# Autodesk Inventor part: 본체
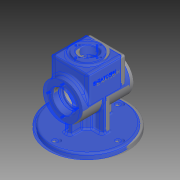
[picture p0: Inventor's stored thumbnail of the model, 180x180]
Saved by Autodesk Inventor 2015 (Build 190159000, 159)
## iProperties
Created: 2020-07
Part Number: 본체
Material: 알루미늄 6061
Document SubType Name: Modeling
Designer: mduedu
Density: 2.71 g/cm^3
Mass: 1025.32 g
Surface Area: 854.574 cm^2
Volume: 378.346 cm^3
Appearance: 기본값
Author: mduedu
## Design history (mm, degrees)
sketch "스케치1"
  geometry: C1 r 32 at (0, 0); 1 further point
  constraints: 1 centre point, 1 coincident
  dimensions: "d0" = 64 diameter of C1
extrude "돌출1" new body sketch "스케치1" stored distance "d1" = 90; taper "d2" = 0 deg
sketch "스케치3"
  geometry: L1 (0, -32)-(50, -32); L2 (50, -32)-(50, 32); L3 (50, 32)-(0, 32); L4 (0, 32)-(0, -32); C1 r 32 at (0, 0) reference; 2 further points
  constraints: 8 end point, 2 parallel, 1 coincident, 1 horizontal, 1 midpoint, 1 perpendicular, 1 tangent
  dimensions: "d5" = 50 distance of L2.end L3.end
extrude "돌출2" join sketch "스케치3" stored distance "d7" = 64; taper "d8" = 0 deg
sketch "스케치4"
  geometry: C1 r 25 at (32, 32); 1 further point
  constraints: 1 centre point, 1 coincident
  dimensions: "d9" = 50 diameter of C1
extrude "돌출3" join sketch "스케치4" distance "d10" = 5; taper "d11" = 0 deg
sketch "스케치5"
  geometry: L1 (0, -25)-(40, -25); L2 (40, -25)-(40, 25); L3 (40, 25)-(0, 25); L4 (0, 25)-(0, -25); L5 (55, -25)-(55, 25) reference; A1 r 25 centre (0, 0) between (0, 25) and (0, -25); A2 r 25 centre (0, 0) between (0, -25) and (0, 25); 2 further points
  constraints: 8 end point, 4 point on circle, 2 centre point, 2 coincident, 2 parallel, 1 horizontal, 1 midpoint, 1 perpendicular, 1 tangent
  dimensions: "d12" = 50 diameter of A1; "d13" = 15 distance between parallel lines of L2 L5
extrude "돌출4" cut sketch "스케치5" stored distance "d14" = 48; taper "d15" = 0 deg
sketch "스케치6"
  geometry: C1 r 20 at (0, 0); 1 further point
  constraints: 1 centre point, 1 coincident
  dimensions: "d16" = 40 diameter of C1
extrude "돌출5" cut sketch "스케치6" distance "d17" = 15; taper "d18" = 0 deg
sketch "스케치7"
  geometry: C1 r 17 at (0, 0); 1 further point
  constraints: 1 centre point, 1 coincident
  dimensions: "d19" = 34 diameter of C1
extrude "돌출6" cut sketch "스케치7" stored distance "d20" = 15; taper "d21" = 0 deg
fillet "모깎기1" dims "d22" = 3
fillet "모깎기2" dims "d23" = 3
fillet "모깎기3" dims "d24" = 3
fillet "모깎기4" dims "d25" = 3
fillet "모깎기5" dims "d26" = 3
sketch "스케치8"
  geometry: C1 r 14 at (0, 0); 1 further point
  constraints: 1 centre point, 1 coincident
  dimensions: "d27" = 28 diameter of C1
extrude "돌출7" cut sketch "스케치8" stored distance "d28" = 15; taper "d29" = 0 deg
node "작업 평면1"
sketch "스케치9"
  geometry: C1 r 67.5 at (0, 0); 1 further point
  constraints: 1 centre point, 1 coincident
  dimensions: "d31" = 135 diameter of C1
extrude "돌출8" join sketch "스케치9" distance "d33" = 10; taper "d34" = 0 deg
sketch "스케치10"
  geometry: C1 r 15 at (0, 0); 1 further point
  constraints: 1 centre point, 1 coincident
  dimensions: "d35" = 30 diameter of C1
extrude "돌출9" join sketch "스케치10" stored distance "d39" = 10; taper "d40" = 0 deg
sketch "스케치11"
  geometry: L1 (-35, -5)-(35, -5); L2 (35, -5)-(35, 5); L3 (35, 5)-(-35, 5); L4 (-35, 5)-(-35, -5); L5 (-35, -5)-(35, 5); L6 (35, -5)-(-35, 5); 1 further point
  constraints: 12 end point, 2 midpoint, 2 parallel, 1 horizontal, 1 perpendicular
  dimensions: "d41" = 70 distance of L3.end L2.end; "d42" = 10 distance of L2.end L1.end
extrude "돌출10" join sketch "스케치11" stored distance "d43" = 10; taper "d44" = 0 deg
sketch "스케치12"
  geometry: L1 (-5, -32)-(5, -32); L2 (5, -32)-(5, 32); L3 (5, 32)-(-5, 32); L4 (-5, 32)-(-5, -32); L5 (-5, -32)-(5, 32); L6 (5, -32)-(-5, 32); 1 further point
  constraints: 12 end point, 2 midpoint, 2 parallel, 1 horizontal, 1 perpendicular
  dimensions: "d45" = 10 distance of L3.end L2.end; "d46" = 64 distance of L2.end L1.end
extrude "돌출11" join sketch "스케치12" stored distance "d47" = 10; taper "d48" = 0 deg
fillet "모깎기6" dims "d50" = 3
fillet "모깎기7" dims "d51" = 3
sketch "스케치13" dims "d52" = 112
  geometry: 3 further points
  constraints: 2 horizontal alignment, 1 coincident, 2 other
hole "구멍1" sketch "스케치13" at (-56, 0) diameter "d54" = 9; stored, may be unused: countersink angle "d58" = 90 deg, drill point angle "d60" = 118 deg; dims "d55" = 6, "d56" = 4, "d57" = 2, "d59" = 8
fillet "모깎기8" dims "d64" = 3
sketch "스케치14" dims "d67" = 50
  geometry: 3 further points
  constraints: 2 vertical alignment, 1 coincident, 2 other
hole "구멍2" sketch "스케치14" at (0, 25) diameter "d68" = 3.242; stored, may be unused: countersink angle "d72" = 90 deg, drill point angle "d74" = 118 deg; dims "d69" = 7, "d70" = 4, "d71" = 2, "d73" = 9
sketch "스케치15" dims "d78" = 38
  geometry: 3 further points
  constraints: 2 vertical alignment, 1 coincident, 2 other
hole "구멍3" sketch "스케치15" at (0, 19) diameter "d79" = 3.242; stored, may be unused: countersink angle "d83" = 90 deg, drill point angle "d85" = 118 deg; dims "d80" = 8, "d81" = 4, "d82" = 2, "d84" = 10
fillet "모깎기9" dims "d89" = 0.3
chamfer "모따기1" distance "d90" = 1; stored, may be unused: second distance "d91" = 2, angle "d92" = 45 deg
chamfer "모따기2" distance "d93" = 1; stored, may be unused: second distance "d94" = 2, angle "d95" = 45 deg
sketch "스케치16"
  geometry: L1 (-3, 0)-(-3, -27.404) reference; L2 (54, 8)-(4, 8) reference; 2 further points
  constraints: 1 other
  dimensions: "d96" = 32 distance from line of point (29, -17) L1; "d97" = 25 distance from line of point (29, -17) L2
feature "엠보싱1" sketch "스케치16" dims "d0" = 64, "d98" = 0.5, "d99" = 0
node "솔리드1"
mirror "대칭1"
pattern_circular "원형 패턴1" dims angle "d62" = 360 deg
pattern_circular "원형 패턴2" dims angle "d76" = 360 deg
mirror "대칭2"
pattern_circular "원형 패턴3" dims angle "d87" = 360 deg
other parameters: "d30" = -65
